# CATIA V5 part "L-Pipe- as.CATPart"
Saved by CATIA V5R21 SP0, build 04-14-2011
Part number: L-Pipe- as
Bounding box of the stored display mesh (mm): x -35 to 0, y -9 to 9, z -9 to 26
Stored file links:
  D:\Koje\수업\Catia\자격증 특강\자격시험예제\Pipe-sample3\L-Pipe- as.CATPart
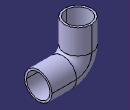
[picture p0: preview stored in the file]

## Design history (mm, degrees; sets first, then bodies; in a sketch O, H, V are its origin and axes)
Body1 (main body)
  Sketch1 on yz-plane, origin (0, 0, 0), H (0, 1, 0), V (0, 0, 1)
    circle A1 centre (0, 0) radius 9
    radius A1 = 9
  Sketch2 on zx-plane, origin (0, 0, 0), H (-1, 0, 0), V (0, 0, 1)
    point P1 (0, 0)
    line L1 (0, 0) -> (16, 0)
    arc A1 centre (16, 10) radius 10 from (16, 0) to (26, 10) ccw
    line L2 (26, 10) -> (26, 26)
    length L1 = 16
    length L2 = 16
    radius A1 = 10
    coincidence: P1 H, P1 V
    horizontal: L1 H
    tangency: L1 A1, L2 A1
    vertical: L2 V
  Rib1: profile Sketch1, centre curve Sketch2
  Sketch3 on yz-plane, origin (0, 0, 0), H (0, 1, 0), V (0, 0, 1)
    circle A1 centre (0, 0) radius 7.75
    radius A1 = 7.75
  Sketch4 on zx-plane, origin (0, 0, 0), H (-1, 0, 0), V (0, 0, 1)
    line L1 (0, 0) -> (16, 0)
    line L2 (26, 10) -> (26, 26)
    arc A1 centre (16, 10) radius 10 from (16, 0) to (26, 10) ccw
    radius A1 = 10
    length L1 = 16
    length L2 = 16
    horizontal: L1 H
    vertical: L2 V
    tangency: A1 L1, A1 L2
  Slot1: profile Sketch3, centre curve Sketch4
